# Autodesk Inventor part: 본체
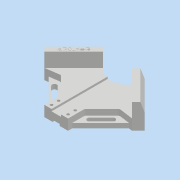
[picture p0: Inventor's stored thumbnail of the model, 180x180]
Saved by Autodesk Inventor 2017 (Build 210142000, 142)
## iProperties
Part Number: 본체
Material: 일반
Document SubType Name: Modeling
Designer: mrc
Density: 1 g/cm^3
Appearance: 기본값
Author: mrc
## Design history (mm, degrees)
node "스케치1"
sketch "스케치2"
  geometry: L1 (0, 0)-(0, 3.931); L2 (20, -64.853)-(84.853, 0); L3 (84.853, 0)-(0, 84.853); L4 (0, 84.853)-(-84.853, 0); L5 (-84.853, 0)-(-20, -64.853); L6 (84.853, 0)-(-84.853, 0); L7 (0, -64.853)-(-20, -64.853); L8 (0, -64.853)-(20, -64.853); L9 (0, 84.853)-(35.355, 49.497); L10 (0, 84.853)-(-35.355, 49.497); L11 (24.749, 38.891)-(74.246, -10.607); L12 (-35.355, 49.497)-(-16.005, 30.147); L13 (35.355, 49.497)-(16.005, 30.147); L14 (-24.749, 38.891)-(-74.246, -10.607); L15 (0, -64.853)-(0, 30.147); L16 (0, 30.147)-(-16.005, 30.147); L17 (0, 30.147)-(16.005, 30.147); L18 (-20, -36.569)-(-49.497, -7.071); L19 (-84.853, 0)-(-63.64, -21.213); L20 (-74.246, -10.607)-(-49.497, -7.071); L21 (84.853, 0)-(63.64, -21.213); L22 (74.246, -10.607)-(49.497, -7.071); L23 (49.497, -7.071)-(20, -36.569); L24 (-20, -64.853)-(-20, -36.569); L25 (20, -64.853)-(20, -36.569); 4 further points
  constraints: 50 end point, 11 point on line, 3 perpendicular, 3 vertical, 2 horizontal, 2 midpoint, 2 parallel
  dimensions: "d10" = 120 distance of L3.end L2.end; "d13" = 20 distance of L7.start L5.end; "d14" = 20 distance of L7.start L2.start; "d15" = 50 distance of L3.end L9.end; "d16" = 50 distance of L3.end L10.end; "d17" = 15 distance between parallel lines of L3 L11; "d19" = 15 distance between parallel lines of L14 L4; "d21" = 20 distance between parallel lines of L5 L18; "d22" = 30 distance of L4.end L19.end; "d24" = 30 distance of L2.end L21.end; "d101" = 95 distance of L7.start L15.end
extrude "돌출1" new body sketch "스케치2" distance "d25" = 18; taper "d26" = 0 deg
sketch "스케치4"
  geometry: L1 (84.853, 0)-(-84.853, 0); L2 (-49.497, -7.071)-(-74.246, -10.607) reference; L3 (-24.749, 38.891)-(-16.005, 30.147) reference; L4 (-74.246, -10.607)-(-24.749, 38.891); L5 (-24.749, 38.891)-(-35.355, 49.497); L6 (24.749, 38.891)-(74.246, -10.607) reference; L7 (24.749, 38.891)-(35.355, 49.497); L8 (24.749, 38.891)-(74.246, -10.607); L9 (-35.355, 49.497)-(-84.853, 0); L10 (-84.853, 0)-(-74.246, -10.607); L11 (35.355, 49.497)-(84.853, 0); L12 (84.853, 0)-(74.246, -10.607); 2 further points
  constraints: 18 end point, 3 perpendicular, 2 midpoint
  dimensions: "d31" = 70 distance of L7.end L1.start
extrude "돌출2" join sketch "스케치4" distance "d32" = 42; taper "d33" = 0 deg
sketch "스케치5"
  geometry: L1 (0, -84.853)-(84.853, 0); L2 (84.853, 0)-(77.782, 0); L3 (-81.317, 3.536)-(-84.853, 0); L4 (84.853, 0)-(81.317, 3.536); L5 (-49.497, -7.071)-(-74.246, -10.607) reference; L6 (-68.059, -9.723)-(-49.497, -7.071); L7 (20, -36.569)-(20, -64.853) reference; L8 (20, -64.853)-(-20, -64.853) reference; L9 (-20, -64.853)-(-20, -36.569) reference; L10 (-20, -36.569)-(-49.497, -7.071) reference; L11 (-49.497, -7.071)-(-74.246, -10.607) reference; L12 (-74.246, -10.607)-(-84.853, 0) reference; L13 (-84.853, 0)-(-35.355, 49.497) reference; L14 (-35.355, 49.497)-(-16.005, 30.147) reference; L15 (-16.005, 30.147)-(16.005, 30.147) reference; L16 (16.005, 30.147)-(35.355, 49.497) reference; L17 (35.355, 49.497)-(84.853, 0) reference; L18 (84.853, 0)-(74.246, -10.607) reference; L19 (74.246, -10.607)-(49.497, -7.071) reference; L20 (49.497, -7.071)-(20, -36.569) reference; L21 (-20, -36.569)-(-49.497, -7.071) reference; L22 (-49.497, -7.071)-(-20, -36.569); L23 (-20, -64.853)-(-20, -36.569) reference; L24 (-20, -36.569)-(-20, -59.093); L25 (20, -36.569)-(20, -64.853) reference; L26 (20, -58.469)-(20, -36.569); L27 (74.246, -10.607)-(49.497, -7.071) reference; L28 (20, -36.569)-(49.497, -7.071); L29 (49.497, -7.071)-(74.246, -10.607); L30 (-84.853, 0)-(-74.246, -10.607); L31 (-20, -64.853)-(0, -84.853); L32 (0, -77.782)-(-12.929, -64.853); L33 (-20, -57.782)-(-68.059, -9.723); L34 (68.059, -9.723)-(20, -57.782); L35 (12.929, -64.853)-(0, -77.782); 2 further points
  constraints: 34 end point, 11 point on line, 4 collinear, 3 parallel, 1 perpendicular, 1 vertical alignment
extrude "돌출3" join sketch "스케치5" distance "d37" = 8; taper "d38" = 0 deg
sketch "스케치6"
  geometry: L1 (16.005, 30.147)-(-16.005, 30.147) reference; L2 (0, 30.147)-(0, -64.853); L3 (-20, -64.853)-(20, -64.853) reference; L4 (-8, 30.147)-(-8, -66.066); L5 (8, 30.147)-(8, -66.066); L6 (8, 30.147)-(-8, 30.147); L7 (-8, -66.066)-(8, -66.066); 1 further point
  constraints: 10 end point, 2 midpoint, 2 parallel, 1 collinear, 1 horizontal
  dimensions: "d39" = 8 distance between parallel lines of L2 L4; "d40" = 8 distance between parallel lines of L2 L5
extrude "돌출4" cut sketch "스케치6" distance "d41" = 3.5; taper "d42" = 0 deg
sketch "스케치7"
  geometry: L1 (20, -64.853)-(-20, -64.853) reference; L2 (0, -64.853)-(0, 30.147); L3 (-16.005, 30.147)-(16.005, 30.147) reference; L4 (6, -66.066)-(6, 30.147); L5 (-6, -66.066)-(-6, 30.147); L6 (-6, 30.147)-(6, 30.147); L7 (6, -66.066)-(-6, -66.066); 1 further point
  constraints: 10 end point, 3 parallel, 2 midpoint, 1 collinear
  dimensions: "d43" = 6 distance between parallel lines of L2 L4; "d44" = 6 distance between parallel lines of L2 L5
extrude "돌출5" cut sketch "스케치7" distance "d45" = 3; taper "d46" = 0 deg
sketch "스케치8"
  geometry: L1 (-20, -36.569)-(-20, -64.853) reference; L2 (-20, -64.853)-(-6, -64.853) reference; L3 (20, -64.853)-(20, -36.569) reference; L4 (8, -64.853)-(20, -64.853) reference; C1 r 2.25 at (14, -46.853); C2 r 2.25 at (14, -58.853); C3 r 2.25 at (-14, -46.853); C4 r 2.25 at (-14, -58.853); 1 further point
  constraints: 4 centre point
  dimensions: "d47" = 4.5 diameter of C1; "d48" = 4.5 diameter of C2; "d49" = 4.5 diameter of C3; "d50" = 4.5 diameter of C4; "d51" = 6 distance from line of L1 C4.centre; "d52" = 6 distance from line of L1 C3.centre; "d53" = 6 distance from line of L2 C4.centre; "d54" = 12 distance of C4.centre C3.centre; "d55" = 6 distance from line of L3 C1.centre; "d56" = 6 distance from line of L3 C2.centre; "d57" = 12 distance of C1.centre C2.centre; "d58" = 6 distance from line of L4 C2.centre
extrude "돌출6" cut sketch "스케치8" distance "d59" = 8; taper "d60" = 0 deg
sketch "스케치9"
  geometry: C1 r 2.25 at (14, -58.853) reference; C2 r 4 at (14, -58.853); C3 r 2.25 at (14, -46.853) reference; C4 r 4 at (14, -46.853); C5 r 2.25 at (-14, -58.853) reference; C6 r 4 at (-14, -58.853); C7 r 2.25 at (-14, -46.853) reference; C8 r 4 at (-14, -46.853); 1 further point
  constraints: 4 centre point, 4 coincident
  dimensions: "d61" = 8 diameter of C2; "d62" = 8 diameter of C4; "d63" = 8 diameter of C6; "d64" = 8 diameter of C8
extrude "돌출7" cut sketch "스케치9" distance "d65" = 10; taper "d66" = 0 deg
sketch "스케치10"
  geometry: L1 (0, 0)-(-5, 0); L2 (-15, 0)-(0, 0) reference; L3 (0, 0)-(0, 15); L4 (0, 15)-(-5, 0); 1 further point
  constraints: 6 end point, 1 point on line, 1 vertical
  dimensions: "d67" = 5 distance of L1.start L1.end; "d68" = 15 distance of L1.start L3.end
extrude "돌출8" cut sketch "스케치10" stored distance "d69" = 10; taper "d70" = 0 deg
sketch "스케치11"
  geometry: L1 (0, 0)-(0, 42) reference; L2 (0, 42)-(-5, 42); L3 (0, 42)-(-15, 42) reference; L4 (0, 42)-(0, 27); L5 (0, 27)-(-5, 42); 1 further point
  constraints: 6 end point, 2 point on line
  dimensions: "d71" = 5 distance of L1.end L2.end; "d72" = 15 distance of L1.end L4.end
extrude "돌출9" cut sketch "스케치11" stored distance "d73" = 10; taper "d74" = 0 deg
sketch "스케치14"
  geometry: L1 (-24.749, 38.891)-(-31.82, 45.962) reference; L2 (31.82, 45.962)-(81.317, -3.536) reference; L3 (81.317, -3.536)-(74.246, -10.607) reference; L4 (74.246, -10.607)-(24.749, 38.891) reference; L5 (24.749, 38.891)-(31.82, 45.962) reference; L6 (-81.317, -3.536)-(-31.82, 45.962) reference; L7 (-31.82, 45.962)-(-24.749, 38.891) reference; L8 (-24.749, 38.891)-(-74.246, -10.607) reference; L9 (-74.246, -10.607)-(-81.317, -3.536) reference; 2 further points
  constraints: 1 other
  dimensions: "d102" = 35 distance from line of point (-53.033, 17.678) L1; "d103" = 5 distance from line of point (-53.033, 17.678) L8
  node "절단 모서리 투영2"
sketch "스케치16"
  geometry: L1 (-74.246, -10.607)-(-84.853, 0) reference; L2 (-52.326, -21.213)-(-46.669, -15.556); L3 (-84.853, 0)-(-76.368, 8.485); L4 (-84.853, 0)-(-35.355, 49.497) reference; L5 (-52.326, -15.556)-(-26.877, -41.006); L6 (-20, -36.569)-(-20, -57.782) reference; L7 (-32.534, -41.006)-(-26.877, -35.349); L8 (-32.534, -41.006)-(-52.326, -21.213); L9 (-76.368, 2.828)-(-82.024, -2.828); L10 (-76.368, 14.142)-(-87.681, 2.828); L11 (-73.539, 11.314)-(-76.368, 14.142); L12 (-17.172, -45.054)-(-20, -42.225); L13 (-26.877, -35.349)-(-46.669, -15.556); A1 r 4 centre (-49.497, -18.385) between (-52.326, -15.556) and (-52.326, -21.213); 2 further points
  constraints: 20 end point, 6 perpendicular, 4 point on line, 2 midpoint, 2 point on circle, 1 centre point, 3 other
  dimensions: "d81" = 12 distance of L1.end L3.end; "d83" = 8 diameter of A1; "d85" = 4 distance between parallel lines of L5 L8
extrude "돌출10" cut sketch "스케치16" stored distance "d87" = 10; taper "d88" = 0 deg
sketch "스케치17"
  geometry: L1 (20, -57.782)-(20, -36.569) reference; L2 (84.853, 0)-(74.246, -10.607) reference; L3 (52.326, -15.556)-(35.355, -32.527); L4 (29.698, -38.184)-(35.355, -32.527); L5 (26.87, -35.355)-(32.527, -29.698); L6 (32.527, -41.012)-(38.184, -35.355); L7 (38.184, -35.355)-(52.326, -21.213); L8 (76.368, 2.828)-(82.024, -2.828); L9 (32.527, -29.698)-(46.669, -15.556); A1 r 4 centre (49.497, -18.385) between (52.326, -21.213) and (46.669, -15.556); A2 r 4 centre (29.698, -38.184) between (26.87, -35.355) and (32.527, -41.012); 1 further point
  constraints: 14 end point, 5 point on circle, 2 centre point, 1 coincident, 1 perpendicular
  dimensions: "d93" = 8 diameter of A1; "d94" = 8 diameter of A2; "d96" = 4 distance between parallel lines of L3 L7
extrude "돌출11" cut sketch "스케치17" stored distance "d97" = 10; taper "d98" = 0 deg
fillet "모깎기1" dims "d99" = 5
fillet "모깎기2" dims "d100" = 5
feature "엠보싱1" dims "d10" = 120, "d13" = 20, "d14" = 20, "d15" = 50, "d16" = 50, "d17" = 15, "d19" = 15, "d21" = 20, "d22" = 30, "d24" = 30, "d26" = 0, "d101" = 95, "d104" = 0.5, "d105" = 0
node "솔리드1"
node "절단 모서리 투영1"
other parameters: "d18" = 15, "d36" = 5, "d86" = 4, "d95" = 4
